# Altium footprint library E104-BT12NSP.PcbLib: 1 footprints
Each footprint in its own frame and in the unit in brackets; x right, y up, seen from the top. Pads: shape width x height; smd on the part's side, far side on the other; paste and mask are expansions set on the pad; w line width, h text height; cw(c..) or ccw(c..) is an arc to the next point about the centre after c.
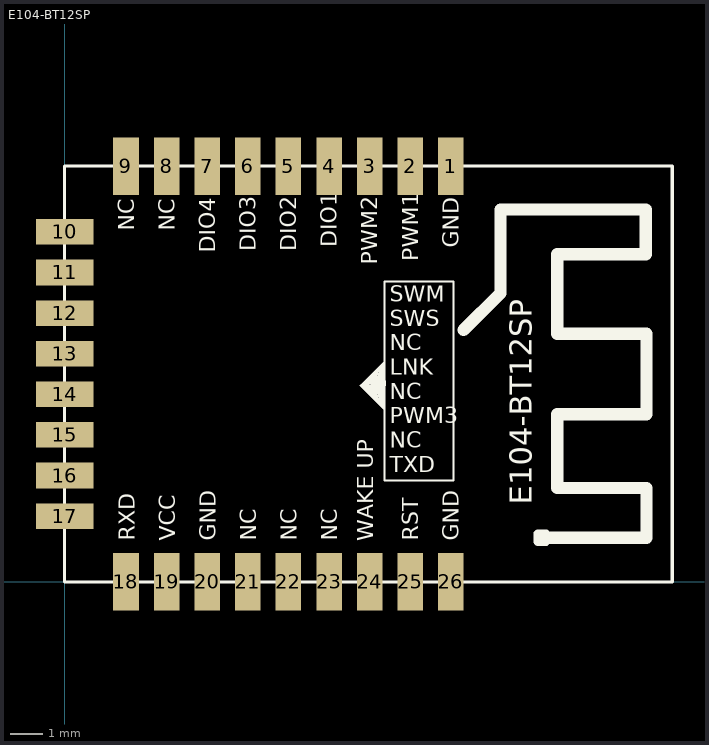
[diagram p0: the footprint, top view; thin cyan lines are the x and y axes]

## E104-BT12SP [mm]
pads (26):
  rect 0.8x1.8 smd: 1(12.075,13) 2(10.805,13) 3(9.535,13) 4(8.265,13) 5(6.995,13) 6(5.725,13) 7(4.455,13) 8(3.185,13) 9(1.915,13) 18(1.915,0) 19(3.185,0) 20(4.455,0) 21(5.725,0) 22(6.995,0) 23(8.265,0) 24(9.535,0) 25(10.805,0) 26(12.075,0)
  rect 1.8x0.8 smd: 10(-0.005,10.945) 11(-0.005,9.675) 12(-0.005,8.405) 13(-0.005,7.135) 14(-0.005,5.865) 15(-0.005,4.595) 16(-0.005,3.325) 17(-0.005,2.055)
Top Overlay:
  lines w0.06: 9.302,6.139 9.452,6.139 ; 9.552,6.089 9.652,5.989 9.702,5.989 9.552,6.139 ; 9.552,6.189 9.652,6.289 9.652,6.139 9.652,6.089 9.602,6.139 9.602,6.189 ; 9.552,6.239 9.752,6.439 9.752,5.889 9.702,5.939 9.702,6.439 9.502,6.239 9.502,6.089 9.802,5.789 9.802,6.539 9.452,6.189 9.452,6.089 9.802,5.739 9.802,5.689 9.852,5.639 9.852,6.639 9.402,6.189 9.402,6.089 9.902,5.589 9.902,6.739 9.352,6.189 9.352,6.089 9.952,5.489 9.952,6.789 ; 10.002,5.389 9.252,6.139 10.002,6.889 ; 10.014,6.14 10.014,6.24 ; 10.014,6.19 10.014,6.29 ; 10.002,3.175 10.002,4.889 10.002,9.398 12.163,9.398 12.163,3.175 10.002,3.175
  lines w0.1: -0.005,0 -0.005,13 18.995,13 18.995,0 -0.005,0
  lines w0.254: 15.045,1.255 14.791,1.255 14.791,1.509 15.045,1.509
  lines w0.381: 12.467,7.872 13.623,9.028 13.623,11.644 18.17,11.644 18.17,10.247 15.401,10.247 15.401,7.758 18.195,7.758 18.195,5.243 15.401,5.243 15.401,2.932 18.195,2.932 18.195,1.382 14.918,1.382
  text "E104-BT12SP" at 14.605,2.413 h0.7
  text "GND" at 4.724,1.291 h0.5
  text "VCC" at 3.458,1.291 h0.5
  text "NC" at 5.99,1.291 h0.5
  text "NC" at 7.257,1.291 h0.5
  text "RXD" at 2.191,1.291 h0.5
  text "NC" at 8.523,1.291 h0.5
  text "WAKE UP" at 9.652,1.27 h0.5
  text "RST" at 11.056,1.291 h0.5
  text "GND" at 12.322,1.291 h0.5
  text "NC" at 2.166,10.983 h0.5
  text "NC" at 3.434,10.983 h0.5
  text "DIO4" at 4.699,10.295 h0.5
  text "DIO3" at 5.971,10.342 h0.5
  text "DIO2" at 7.239,10.342 h0.5
  text "DIO1" at 8.509,10.461 h0.5
  text "PWM2" at 9.779,9.914 h0.5
  text "PWM1" at 11.049,10.033 h0.5
  text "GND" at 12.313,10.442 h0.5
  text "TXD" at 10.16,3.429 h0.5
  text "NC" at 10.16,4.191 h0.5
  text "PWM3" at 10.16,4.953 h0.5
  text "NC" at 10.16,5.715 h0.5
  text "LNK" at 10.16,6.477 h0.5
  text "NC" at 10.16,7.239 h0.5
  text "SWM" at 10.16,8.763 h0.5
  text "SWS" at 10.16,8.001 h0.5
